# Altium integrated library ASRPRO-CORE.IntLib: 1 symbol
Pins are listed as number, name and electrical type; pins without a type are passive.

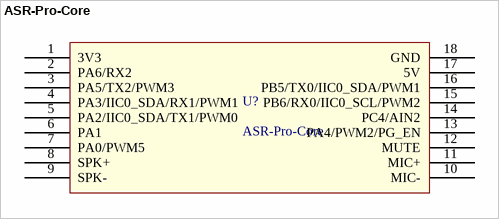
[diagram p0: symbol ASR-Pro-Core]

## ASR-Pro-Core
designator U?
footprint TW-ASR-Pro-Core
pins: 1 3V3, 2 PA6/RX2, 3 PA5/TX2/PWM3, 4 PA3/IIC0_SDA/RX1/PWM1, 5 PA2/IIC0_SDA/TX1/PWM0, 6 PA1, 7 PA0/PWM5, 8 SPK+, 9 SPK-, 10 MIC-, 11 MIC+, 12 MUTE, 13 PA4/PWM2/PG_EN, 14 PC4/AIN2, 15 PB6/RX0/IIC0_SCL/PWM2, 16 PB5/TX0/IIC0_SDA/PWM1, 17 5V, 18 GND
